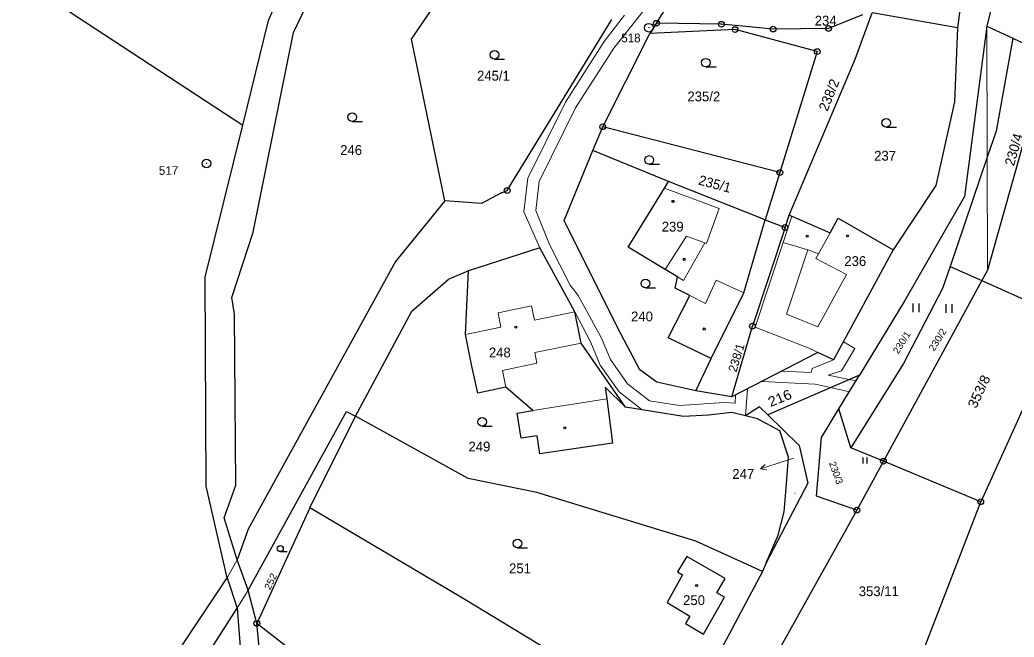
# Model space of a CAD drawing. Extents: x -504006 to -501322, y -1128098 to -1124665.
# Drawn here: x -502830.4 to -502657.9, y -1127003.9 to -1126896.8 of the extents above; entities that cross this region are included whole.
import ezdxf
from ezdxf.enums import TextEntityAlignment as Align

# ---------------------------------------------------------------- set-up
doc = ezdxf.new("R2010")
doc.units = 0
doc.header["$LTSCALE"] = 0.68
for name, color, linetype, lineweight in [('1', 7, 'Continuous', 25), ('13', 7, 'Continuous', 13), ('3', 7, 'Continuous', 25), ('4', 7, 'Continuous', 13), ('5', 7, 'Continuous', 25), ('7', 7, 'Continuous', 13), ('8', 7, 'Continuous', 25)]:
    doc.layers.add(name, color=color, linetype=linetype, lineweight=lineweight)
doc.layers.add('2', color=7, linetype='Continuous')

msp = doc.modelspace()

# ---------------------------------------------------------------- linework, layer by layer
at = {"layer": '1'}
for p, q in [((-502787.25, -1126896.89), (-502771.06, -1126859.54)), ((-502656.38, -1126871.93), (-502662.64, -1126897.84)), ((-502782.92, -1126898.96), (-502772.27, -1126876.65)), ((-502762.47, -1126900.11), (-502748.28, -1126879.25)), ((-502665.88, -1126883.34), (-502667.76, -1126898.12)), ((-502836.17, -1126885.85), (-502791.71, -1126915.01)), ((-502719.97, -1126897.34), (-502717.98, -1126894.23)), ((-502684.22, -1126895.87), (-502690.13, -1126898.25)), ((-502685.5, -1126903.59), (-502682.57, -1126895.54)), ((-502667.76, -1126898.12), (-502682.57, -1126895.54)), ((-502791.71, -1126915.01), (-502787.25, -1126896.89)), ((-502745.83, -1126926.36), (-502727.7, -1126896.67)), ((-502719.97, -1126897.34), (-502721.13, -1126899.14)), ((-502708.71, -1126897.51), (-502719.97, -1126897.34)), ((-502699.73, -1126898.35), (-502708.71, -1126897.51)), ((-502662.64, -1126897.84), (-502666.53, -1126927.38)), ((-502662.64, -1126897.84), (-502658.16, -1126899.95)), ((-502789.88, -1126933.59), (-502782.92, -1126898.96)), ((-502729.29, -1126915.3), (-502721.13, -1126899.14)), ((-502706.33, -1126898.44), (-502721.13, -1126899.14)), ((-502692.07, -1126902.27), (-502706.33, -1126898.44)), ((-502690.13, -1126898.25), (-502699.73, -1126898.35)), ((-502667.76, -1126898.12), (-502668.27, -1126910.97)), ((-502756.66, -1126928.18), (-502762.47, -1126900.11)), ((-502658.16, -1126899.95), (-502661.05, -1126916.05)), ((-502658.16, -1126899.95), (-502652.07, -1126902.81)), ((-502692.07, -1126902.27), (-502698.56, -1126923.22)), ((-502652.07, -1126902.81), (-502662.54, -1126940.17)), ((-502696.96, -1126930.64), (-502685.5, -1126903.59)), ((-502668.27, -1126910.97), (-502671.51, -1126925.48)), ((-502798.21, -1126941.39), (-502791.71, -1126915.01)), ((-502730.99, -1126919.45), (-502729.29, -1126915.3)), ((-502698.56, -1126923.22), (-502729.29, -1126915.3)), ((-502661.05, -1126916.05), (-502662.59, -1126920.57)), ((-502735.96, -1126931.57), (-502730.99, -1126919.45)), ((-502717.89, -1126924.83), (-502730.99, -1126919.45)), ((-502662.59, -1126920.57), (-502669.04, -1126939.55)), ((-502698.56, -1126923.22), (-502701.1, -1126931.43)), ((-502718.59, -1126925.94), (-502717.89, -1126924.83)), ((-502701.1, -1126931.43), (-502717.89, -1126924.83)), ((-502671.51, -1126925.48), (-502678.89, -1126936.67)), ((-502746.86, -1126926.76), (-502750.28, -1126928.64)), ((-502746.86, -1126926.76), (-502745.83, -1126926.36)), ((-502724.87, -1126936.19), (-502718.59, -1126925.94)), ((-502756.66, -1126928.18), (-502765.22, -1126938.69)), ((-502750.28, -1126928.64), (-502756.66, -1126928.18)), ((-502666.53, -1126927.38), (-502676.88, -1126945.43)), ((-502697.67, -1126932.78), (-502696.96, -1126930.64)), ((-502696.96, -1126930.64), (-502696.5, -1126930.84)), ((-502726.68, -1126950.27), (-502735.96, -1126931.57)), ((-502704.81, -1126944.11), (-502701.1, -1126931.43)), ((-502701.1, -1126931.43), (-502697.67, -1126932.78)), ((-502696.5, -1126930.84), (-502689.85, -1126933.73)), ((-502689.85, -1126933.73), (-502688.43, -1126931.15)), ((-502688.43, -1126931.15), (-502678.89, -1126936.67)), ((-502793.59, -1126944.94), (-502789.88, -1126933.59)), ((-502697.67, -1126932.78), (-502703.33, -1126949.9)), ((-502740.17, -1126936.34), (-502752.57, -1126940.31)), ((-502734.12, -1126947.44), (-502740.17, -1126936.34)), ((-502718.43, -1126940.09), (-502724.87, -1126936.19)), ((-502678.89, -1126936.67), (-502689.25, -1126955.77)), ((-502765.22, -1126938.69), (-502790.77, -1126985.15)), ((-502752.57, -1126940.31), (-502756.1, -1126941.83)), ((-502753.11, -1126951.35), (-502752.57, -1126940.31)), ((-502716.32, -1126941.37), (-502718.43, -1126940.09)), ((-502669.04, -1126939.55), (-502670.35, -1126943.36)), ((-502669.04, -1126939.55), (-502663.54, -1126942)), ((-502662.54, -1126940.17), (-502663.54, -1126942)), ((-502798.07, -1126977.66), (-502798.21, -1126941.39)), ((-502762.41, -1126947.28), (-502756.1, -1126941.83)), ((-502716.74, -1126943.31), (-502716.32, -1126941.37)), ((-502663.54, -1126942), (-502680.6, -1126973.35)), ((-502663.54, -1126942), (-502649.24, -1126948.37)), ((-502714.2, -1126944.6), (-502716.74, -1126943.31)), ((-502710.45, -1126955.53), (-502704.81, -1126944.11)), ((-502670.35, -1126943.36), (-502677.14, -1126956.4)), ((-502793.17, -1126947.8), (-502793.59, -1126944.94)), ((-502717.93, -1126951.93), (-502714.2, -1126944.6)), ((-502676.88, -1126945.43), (-502684.76, -1126958.4)), ((-502792.89, -1126977.48), (-502793.17, -1126947.8)), ((-502772.18, -1126965.55), (-502762.41, -1126947.28)), ((-502733.01, -1126952.83), (-502734.12, -1126947.44)), ((-502649.24, -1126948.37), (-502663.72, -1126980.38)), ((-502751.96, -1126956.84), (-502753.11, -1126951.35)), ((-502722.82, -1126957.48), (-502726.68, -1126950.27)), ((-502706.87, -1126962.19), (-502703.33, -1126949.9)), ((-502725.31, -1126963.95), (-502733.01, -1126952.83)), ((-502710.45, -1126955.53), (-502717.93, -1126951.93)), ((-502691.95, -1126954.48), (-502706.87, -1126962.19)), ((-502689.25, -1126955.77), (-502691.95, -1126954.48)), ((-502713.14, -1126961.11), (-502710.45, -1126955.53)), ((-502677.14, -1126956.4), (-502686.25, -1126971)), ((-502750.96, -1126961.54), (-502751.96, -1126956.84)), ((-502719.92, -1126959.62), (-502722.82, -1126957.48)), ((-502713.14, -1126961.11), (-502719.92, -1126959.62)), ((-502684.76, -1126958.4), (-502700.66, -1126965.28)), ((-502688.31, -1126964.23), (-502684.76, -1126958.4)), ((-502746.07, -1126960.51), (-502750.96, -1126961.54)), ((-502741.38, -1126964.55), (-502746.07, -1126960.51)), ((-502728.85, -1126960.48), (-502728.58, -1126962.51)), ((-502725.31, -1126963.95), (-502728.85, -1126960.48)), ((-502706.87, -1126962.19), (-502713.14, -1126961.11)), ((-502728.58, -1126962.51), (-502727.57, -1126970.22)), ((-502790.78, -1126995.71), (-502773.71, -1126964.71)), ((-502773.71, -1126964.71), (-502772.18, -1126965.55)), ((-502744.14, -1126964.99), (-502741.38, -1126964.55)), ((-502743.45, -1126969.36), (-502744.14, -1126964.99)), ((-502715.3, -1126965.57), (-502725.31, -1126963.95)), ((-502706.87, -1126964.87), (-502710.94, -1126965.36)), ((-502704.5, -1126965.48), (-502706.87, -1126964.87)), ((-502702.09, -1126963.88), (-502704.5, -1126965.48)), ((-502700.66, -1126965.28), (-502702.09, -1126963.88)), ((-502691.33, -1126969.21), (-502688.31, -1126964.23)), ((-502686.25, -1126971), (-502688.31, -1126964.23)), ((-502780.05, -1126981.41), (-502772.18, -1126965.55)), ((-502752.62, -1126976.32), (-502772.18, -1126965.55)), ((-502710.94, -1126965.36), (-502715.3, -1126965.57)), ((-502702.46, -1126966), (-502704.5, -1126965.48)), ((-502698.55, -1126968.07), (-502702.46, -1126966)), ((-502700.66, -1126965.28), (-502695.2, -1126970.59)), ((-502697.08, -1126972.65), (-502698.55, -1126968.07)), ((-502740.68, -1126968.91), (-502743.45, -1126969.36)), ((-502740.18, -1126972.08), (-502740.68, -1126968.91)), ((-502727.57, -1126970.22), (-502740.18, -1126972.08)), ((-502692.22, -1126979.4), (-502691.33, -1126969.21)), ((-502695.2, -1126970.59), (-502693.7, -1126977.14)), ((-502680.6, -1126973.35), (-502686.25, -1126971)), ((-502697.43, -1126977.27), (-502697.08, -1126972.65)), ((-502680.6, -1126973.35), (-502685.21, -1126981.83)), ((-502663.72, -1126980.38), (-502680.6, -1126973.35)), ((-502740.71, -1126978.78), (-502752.62, -1126976.32)), ((-502693.7, -1126977.14), (-502700.93, -1126990.95)), ((-502697.82, -1126982.14), (-502697.43, -1126977.27)), ((-502794.44, -1126993.56), (-502798.07, -1126977.66)), ((-502794.94, -1126983.19), (-502792.89, -1126977.48)), ((-502713.16, -1126987.21), (-502740.71, -1126978.78)), ((-502685.21, -1126981.83), (-502692.22, -1126979.4)), ((-502678.51, -1127018.76), (-502663.72, -1126980.38)), ((-502780.05, -1126981.41), (-502789.27, -1127001.48)), ((-502752.9, -1126997.52), (-502780.05, -1126981.41)), ((-502685.21, -1126981.83), (-502698.9, -1127006.42)), ((-502698.84, -1126986.2), (-502697.82, -1126982.14)), ((-502792.66, -1126990.44), (-502794.94, -1126983.19)), ((-502790.77, -1126985.15), (-502792.66, -1126990.44)), ((-502701.6, -1126992.5), (-502713.16, -1126987.21)), ((-502700.93, -1126990.95), (-502698.84, -1126986.2)), ((-502790.78, -1126995.71), (-502792.66, -1126990.44)), ((-502714.71, -1126989.85), (-502716.34, -1126992.55)), ((-502708.04, -1126993.67), (-502714.71, -1126989.85)), ((-502700.93, -1126990.95), (-502701.6, -1126992.5)), ((-502716.34, -1126992.55), (-502715.43, -1126993.06)), ((-502701.6, -1126992.5), (-502712.32, -1127012.6)), ((-502830.12, -1127047.35), (-502794.44, -1126993.56)), ((-502794.44, -1126993.56), (-502792.68, -1126998.83)), ((-502715.43, -1126993.06), (-502718.11, -1126997.88)), ((-502709.47, -1126996.18), (-502708.04, -1126993.67)), ((-502789.27, -1127001.48), (-502790.78, -1126995.71)), ((-502708.15, -1126996.92), (-502709.47, -1126996.18)), ((-502726.47, -1127013.56), (-502752.9, -1126997.52)), ((-502718.11, -1126997.88), (-502714.17, -1127000.22)), ((-502711.82, -1127003.35), (-502708.15, -1126996.92)), ((-502823.66, -1127047.34), (-502792.68, -1126998.83)), ((-502792.68, -1126998.83), (-502788.22, -1127058.48)), ((-502714.17, -1127000.22), (-502714.92, -1127001.52)), ((-502768.42, -1127017.71), (-502789.27, -1127001.48)), ((-502783.5, -1127057.54), (-502789.27, -1127001.48)), ((-502714.92, -1127001.52), (-502711.82, -1127003.35))]:
    msp.add_line(p, q, dxfattribs=at)
at = {"layer": '13'}
for points in [[(-502704.5, -1126965.48), (-502704.15, -1126960.79), (-502706.23, -1126961.86), (-502706.31, -1126963.28), (-502708.21, -1126963.17), (-502715.98, -1126963.7), (-502721.19, -1126962.85), (-502724.98, -1126959.93), (-502727.94, -1126955.7), (-502729.54, -1126951.88), (-502733.52, -1126944.58), (-502734.93, -1126942.8), (-502738.51, -1126935.74), (-502740.91, -1126929.81), (-502740.33, -1126924.79), (-502733.99, -1126912.02), (-502727.38, -1126901.69), (-502719.38, -1126891.53)], [(-502725.52, -1126895.93), (-502729.02, -1126900.53), (-502735.73, -1126911.04), (-502742.27, -1126924.21), (-502742.95, -1126930.09), (-502740.17, -1126936.34), (-502734.12, -1126947.44), (-502731.34, -1126952.74), (-502729.7, -1126956.67), (-502726.44, -1126961.33), (-502722.44, -1126964.41), (-502715.3, -1126965.57), (-502710.94, -1126965.36), (-502706.87, -1126964.87), (-502704.5, -1126965.48)]]:
    msp.add_lwpolyline(points, dxfattribs=at)
msp.add_lwpolyline([(-502687.55, -1126952.64), (-502689.25, -1126955.77), (-502692.94, -1126957.23), (-502693.12, -1126957.95), (-502698.25, -1126957.74), (-502701.65, -1126959.49), (-502692.46, -1126959.98), (-502689.76, -1126960.57), (-502686.51, -1126961.28), (-502685.37, -1126959.4), (-502686.53, -1126959.17), (-502690.18, -1126958.43), (-502687.87, -1126957.66), (-502685.58, -1126953.8)], close=True, dxfattribs=at)
at = {"layer": '3'}
for p, q in [((-502748.043, -1126903.56), (-502746.293, -1126903.56)), ((-502711.383, -1126904.93), (-502709.633, -1126904.93)), ((-502772.713, -1126914.37), (-502770.963, -1126914.37)), ((-502680.103, -1126915.36), (-502678.353, -1126915.36)), ((-502721.203, -1126921.82), (-502719.453, -1126921.82)), ((-502721.883, -1126943.26), (-502720.133, -1126943.26)), ((-502675.421, -1126947.49), (-502675.421, -1126945.99)), ((-502674.42, -1126947.49), (-502674.42, -1126945.99)), ((-502669.691, -1126947.57), (-502669.691, -1126946.07)), ((-502668.69, -1126947.57), (-502668.69, -1126946.07)), ((-502750.203, -1126967.27), (-502748.453, -1126967.27)), ((-502684.138, -1126973.76), (-502684.138, -1126972.71)), ((-502683.437, -1126973.76), (-502683.437, -1126972.71)), ((-502785.215, -1126989.03), (-502783.99, -1126989.03)), ((-502744.063, -1126988.36), (-502742.313, -1126988.36))]:
    msp.add_line(p, q, dxfattribs=at)
for centre, radius in [((-502748.0429, -1126902.8098), 0.75), ((-502711.3829, -1126904.1798), 0.75), ((-502772.7129, -1126913.6198), 0.75), ((-502680.1029, -1126914.6098), 0.75), ((-502721.2029, -1126921.0698), 0.75), ((-502721.8829, -1126942.5098), 0.75), ((-502750.2029, -1126966.5198), 0.75), ((-502744.0629, -1126987.6098), 0.75), ((-502785.215, -1126988.5049), 0.525)]:
    msp.add_circle(centre, radius, dxfattribs=at)
at = {"layer": '4'}
for p, q in [((-502662.64, -1126897.84), (-502662.59, -1126920.57)), ((-502662.59, -1126920.57), (-502662.54, -1126940.17)), ((-502718.59, -1126925.94), (-502709.07, -1126929.49)), ((-502709.07, -1126929.49), (-502711.3, -1126935.54)), ((-502698, -1126935.39), (-502696.5, -1126930.84)), ((-502691.85, -1126937.34), (-502689.85, -1126933.73)), ((-502714.75, -1126934.27), (-502718.43, -1126940.09)), ((-502711.58, -1126935.44), (-502715.29, -1126941.99)), ((-502711.58, -1126935.44), (-502714.75, -1126934.27)), ((-502711.3, -1126935.54), (-502711.58, -1126935.44)), ((-502702.87, -1126950.09), (-502698, -1126935.39)), ((-502698, -1126935.39), (-502693.71, -1126936.64)), ((-502693.71, -1126936.64), (-502697.41, -1126947.85)), ((-502691.85, -1126937.34), (-502693.71, -1126936.64)), ((-502692.32, -1126938.18), (-502691.85, -1126937.34)), ((-502687.02, -1126940.95), (-502692.32, -1126938.18)), ((-502691.97, -1126950), (-502687.02, -1126940.95)), ((-502715.29, -1126941.99), (-502716.32, -1126941.37)), ((-502711.48, -1126945.99), (-502709.6, -1126941.9)), ((-502709.6, -1126941.9), (-502704.81, -1126944.11)), ((-502714.2, -1126944.6), (-502711.48, -1126945.99)), ((-502747.44, -1126947.57), (-502741.66, -1126946.37)), ((-502746.93, -1126950.08), (-502747.44, -1126947.57)), ((-502741.66, -1126946.37), (-502741.14, -1126948.89)), ((-502741.14, -1126948.89), (-502734.12, -1126947.44)), ((-502697.41, -1126947.85), (-502691.97, -1126950)), ((-502753.11, -1126951.35), (-502746.93, -1126950.08)), ((-502693.39, -1126953.8), (-502702.87, -1126950.09)), ((-502733.01, -1126952.83), (-502741.08, -1126954.49)), ((-502741.08, -1126954.49), (-502740.7, -1126956.32)), ((-502691.95, -1126954.48), (-502693.39, -1126953.8)), ((-502740.7, -1126956.32), (-502746.69, -1126957.58)), ((-502746.69, -1126957.58), (-502746.07, -1126960.51)), ((-502741.38, -1126964.55), (-502728.58, -1126962.51)), ((-502792.66, -1126990.44), (-502794.44, -1126993.56)), ((-502792.68, -1126998.83), (-502790.78, -1126995.71))]:
    msp.add_line(p, q, dxfattribs=at)
at = {"layer": '5'}
for centre in [(-502717.0868, -1126928.2492), (-502693.8168, -1126934.2992), (-502686.8168, -1126934.2292), (-502715.1468, -1126938.3092), (-502744.3368, -1126950.0992), (-502711.6868, -1126950.3992), (-502735.8668, -1126967.5492), (-502712.9968, -1126994.9192)]:
    msp.add_circle(centre, 0.175, dxfattribs=at)
at = {"layer": '7'}
msp.add_line((-502701.904, -1126974.677), (-502700.797, -1126974.844), dxfattribs=at)
msp.add_lwpolyline([(-502696.21, -1126972.81), (-502699.05, -1126973.75), (-502701.904, -1126974.677), (-502701.106, -1126973.892)], dxfattribs=at)
at = {"layer": '8'}
for centre, radius in [((-502721.28, -1126898.1098), 0.75), ((-502719.97, -1126897.3399), 0.5), ((-502719.97, -1126897.3399), 0.0303), ((-502708.71, -1126897.5099), 0.5), ((-502708.71, -1126897.5099), 0.0303), ((-502706.33, -1126898.4399), 0.5), ((-502699.73, -1126898.3499), 0.5), ((-502690.13, -1126898.2499), 0.5), ((-502721.28, -1126898.1098), 0.03), ((-502706.33, -1126898.4399), 0.0303), ((-502699.73, -1126898.3499), 0.0303), ((-502690.13, -1126898.2499), 0.0303), ((-502692.07, -1126902.2699), 0.5), ((-502692.07, -1126902.2699), 0.0303), ((-502729.29, -1126915.2999), 0.5), ((-502729.29, -1126915.2999), 0.0303), ((-502798, -1126921.6698), 0.75), ((-502798, -1126921.6698), 0.03), ((-502698.56, -1126923.2199), 0.5), ((-502698.56, -1126923.2199), 0.0303), ((-502745.83, -1126926.3599), 0.5), ((-502745.83, -1126926.3599), 0.0303), ((-502697.67, -1126932.7799), 0.5), ((-502697.67, -1126932.7799), 0.0303), ((-502703.33, -1126949.8999), 0.5), ((-502703.33, -1126949.8999), 0.0303), ((-502680.6, -1126973.3499), 0.5), ((-502680.6, -1126973.3499), 0.0303), ((-502663.72, -1126980.3799), 0.5), ((-502663.72, -1126980.3799), 0.0303), ((-502685.21, -1126981.8299), 0.5), ((-502685.21, -1126981.8299), 0.0303), ((-502789.27, -1127001.4799), 0.5), ((-502789.27, -1127001.4799), 0.0303)]:
    msp.add_circle(centre, radius, dxfattribs=at)

# ---------------------------------------------------------------- texts
at = {"layer": '2'}
for s, p in [('234', (-502690.619, -1126897.735)), ('245/1', (-502748.24, -1126907.295)), ('235/2', (-502711.75, -1126910.895)), ('246', (-502772.919, -1126920.195)), ('237', (-502680.309, -1126921.185)), ('239', (-502717.149, -1126933.485)), ('236', (-502685.489, -1126939.465)), ('240', (-502722.469, -1126949.075)), ('248', (-502747.129, -1126955.325)), ('249', (-502750.669, -1126971.655)), ('251', (-502743.629, -1126992.785)), ('353/11', (-502681.41, -1126996.755))]:
    msp.add_text(s, height=1.7, dxfattribs=at).set_placement(p, align=Align.CENTER)
for s, height, rotation, p in [('238/2', 1.7, 68, (-502689.2501, -1126910.0964)), ('230/4', 1.7, 74, (-502657.1871, -1126919.4978)), ('235/1', 1.7, 345, (-502710.048, -1126926.0399)), ('238/1', 1.5, 73, (-502705.3772, -1126955.5973)), ('230/3', 1.2, 290, (-502689.3732, -1126975.5668)), ('247', 0.2, 85, (-502695.8392, -1126978.9687))]:
    msp.add_text(s, height=height, rotation=rotation, dxfattribs=at).set_placement(p, align=Align.CENTER)
for s, height, rotation, width, p in [('230/1', 1.2, 58, 1.05, (-502676.914, -1126953.0565)), ('230/2', 1.2, 58, 1.05, (-502670.704, -1126952.5765)), ('353/8', 1.7, 65, 1.05, (-502663.2591, -1126961.6057)), ('216', 1.7, 22, 1.1, (-502698.2489, -1126963.1683)), ('252', 1.2, 65, 1.1, (-502786.3379, -1126994.4576))]:
    msp.add_text(s, height=height, rotation=rotation, dxfattribs=dict(at, width=width)).set_placement(p, align=Align.CENTER)
msp.add_text('247', height=1.7, dxfattribs=at).set_placement((-502703.009, -1126976.402), align=Align.RIGHT)
msp.add_text('250', height=1.7, dxfattribs=at).set_placement((-502715.34, -1126998.305))
at = {"layer": '8'}
for s, p in [('518', (-502722.719, -1126900.637)), ('517', (-502802.909, -1126923.645))]:
    msp.add_text(s, height=1.5, dxfattribs=at).set_placement(p, align=Align.RIGHT)

doc.saveas('drawing.dxf')
